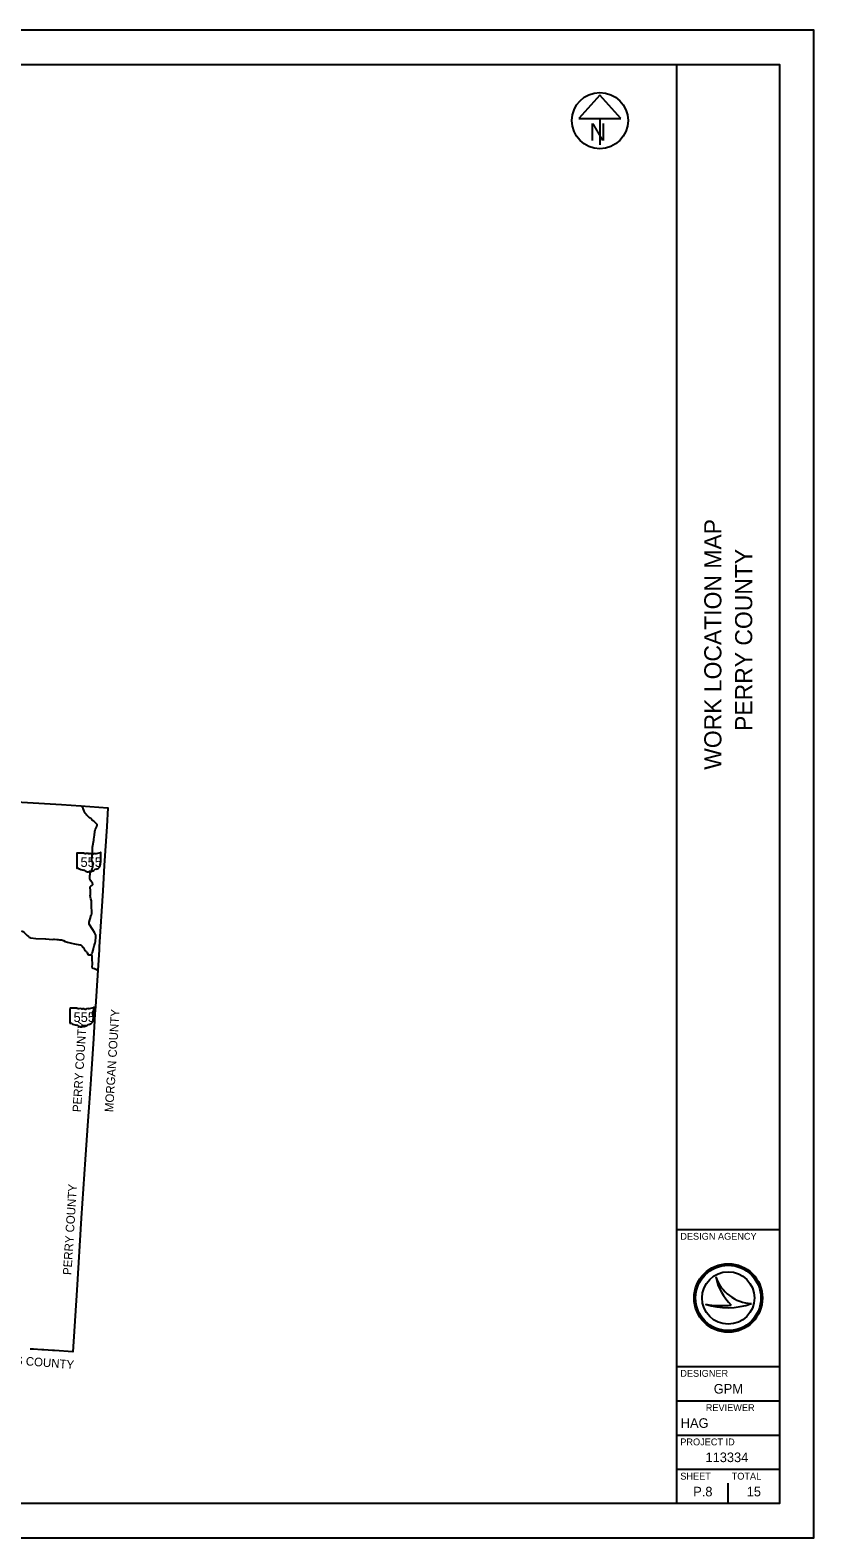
# Model space of a CAD drawing. Extents: x 1912787 to 2184787, y 78841 to 719251.
# Drawn here: x 2093246 to 2184787, y 543251 to 719251 of the extents above; entities that cross this region are included whole.
import ezdxf

# ---------------------------------------------------------------- set-up
doc = ezdxf.new("R2010")
doc.units = 0
for name, color, linetype in [('GM_X_County', 7, 'Continuous'), ('GM_X_County_Text', 7, 'Continuous'), ('GM_X_State_Location', 7, 'Continuous'), ('GM_X_State_Route', 7, 'Continuous'), ('GM_X_State_Shield', 7, 'Continuous'), ('SH_Border', 7, 'Continuous'), ('SH_Cut_Line', 7, 'Continuous'), ('SH_Data', 7, 'Continuous'), ('SH_Masking', 7, 'Continuous'), ('SH_Text', 7, 'Continuous')]:
    doc.layers.add(name, color=color, linetype=linetype)

msp = doc.modelspace()

# ---------------------------------------------------------------- linework, layer by layer
at = {"layer": 'GM_X_County'}
msp.add_lwpolyline([(2090938, 629224), (2096895, 628847), (2099187, 628710), (2102312, 628487), (2102193, 626283), (2101908, 621725), (2101721, 618763), (2101311, 612237), (2101290, 611908), (2101137, 609504), (2100881, 605294), (2100816, 604427), (2100776, 603648), (2100631, 601508), (2100343, 596816), (2100327, 596770), (2100147, 594037), (2099987, 591925), (2099681, 587430), (2099218, 580571), (2098707, 572170), (2098250, 564948), (2096075, 565106), (2095873, 565126), (2094827, 565192), (2094797, 565200), (2094779, 565204), (2094764, 565207), (2094750, 565209), (2094740, 565211), (2094727, 565212), (2094716, 565212), (2094701, 565213), (2094683, 565212), (2094668, 565211), (2094648, 565210), (2094631, 565207), (2094613, 565204), (2093651, 565260), (2093610, 565267), (2093571, 565272), (2093538, 565275), (2093505, 565278), (2093473, 565281), (2093444, 565283), (2093421, 565284), (2093383, 565286), (2093357, 565287), (2093335, 565287), (2093279, 565284), (2093242, 565282)], dxfattribs=at)
at = {"layer": 'GM_X_State_Route'}
for points in [[(2099600, 627994), (2099570, 628077), (2099522, 628214), (2099451, 628392), (2099374, 628518), (2099298, 628605), (2099188, 628707)], [(2101076, 626465), (2101081, 626479), (2101088, 626513), (2100994, 626609), (2100806, 626799), (2100700, 626898), (2100545, 626998), (2100502, 627052), (2100472, 627100), (2100453, 627131), (2100427, 627169), (2100408, 627187), (2100370, 627213), (2100312, 627242), (2100254, 627266), (2100196, 627297), (2100151, 627330), (2100111, 627364), (2099976, 627498), (2099922, 627559), (2099883, 627610), (2099831, 627677), (2099793, 627720), (2099748, 627765), (2099661, 627851), (2099626, 627921), (2099600, 627994)], [(2100572, 621814), (2100571, 621851), (2100568, 621979), (2100564, 622050), (2100492, 622189), (2100433, 622306), (2100418, 622362), (2100421, 622417), (2100438, 622470), (2100450, 622524), (2100481, 622839), (2100512, 623284), (2100512, 623462), (2100543, 623875), (2100669, 624702), (2100686, 624812), (2100760, 625292), (2100818, 625708), (2100851, 625884), (2100904, 626052), (2101021, 626309), (2101076, 626465)], [(2100227, 620259), (2100227, 620264), (2100229, 620349), (2100237, 620530), (2100238, 620563), (2100243, 620639), (2100243, 620701), (2100248, 620763), (2100256, 620821), (2100264, 620861), (2100289, 620950), (2100298, 620979), (2100310, 621008), (2100324, 621040), (2100336, 621063), (2100346, 621082), (2100374, 621129), (2100438, 621236), (2100484, 621313), (2100499, 621347), (2100508, 621372), (2100524, 621411), (2100538, 621450), (2100548, 621475), (2100552, 621492), (2100557, 621524), (2100560, 621544), (2100562, 621562), (2100566, 621601), (2100569, 621651), (2100569, 621699), (2100573, 621771), (2100572, 621814)], [(2100408, 611276), (2100464, 611414), (2100522, 611579), (2100591, 611844), (2100652, 612054), (2100742, 612343), (2100851, 612691), (2100894, 612858), (2100934, 613401), (2100932, 613525), (2100914, 613602), (2100870, 613699), (2100765, 613917), (2100585, 614226), (2100150, 614888), (2100131, 614961), (2100158, 615103), (2100330, 615799), (2100339, 615853), (2100350, 615895), (2100407, 616002), (2100438, 616062), (2100460, 616142), (2100427, 617136), (2100421, 617330), (2100428, 617496), (2100415, 617625), (2100354, 617832), (2100302, 618054), (2100274, 618180), (2100298, 618326), (2100309, 618521), (2100282, 618858), (2100241, 619116), (2100244, 619190), (2100271, 619254), (2100323, 619321), (2100558, 619494), (2100573, 619505), (2100586, 619514), (2100524, 619673), (2100407, 619847), (2100336, 619933), (2100281, 620014), (2100242, 620104), (2100237, 620123), (2100232, 620154), (2100228, 620186), (2100227, 620219), (2100227, 620259)], [(2092257, 614093), (2092407, 614019), (2092552, 613916), (2092757, 613724), (2092892, 613584), (2093069, 613433), (2093147, 613380), (2093234, 613338), (2093291, 613301), (2093344, 613282)], [(2093344, 613282), (2093921, 613233), (2095034, 613160)], [(2095034, 613160), (2095087, 613157), (2095851, 613117), (2096017, 613132), (2096109, 613128), (2096378, 613103), (2096525, 613096), (2096675, 613073), (2096929, 613058), (2097023, 613035), (2097154, 612983), (2097348, 612871), (2097595, 612783), (2098082, 612674), (2098421, 612602), (2098618, 612563), (2098871, 612516), (2099060, 612491), (2099171, 612457), (2099254, 612416), (2099326, 612338), (2099417, 612202), (2099470, 612148), (2099507, 612108), (2099565, 611968), (2099638, 611820), (2099691, 611762), (2099778, 611682), (2099849, 611607), (2099902, 611527), (2100011, 611349), (2100089, 611326), (2100275, 611300), (2100361, 611290), (2100408, 611276)], [(2100408, 611276), (2100432, 611248), (2100439, 611215), (2100444, 611101), (2100460, 610757), (2100484, 610316), (2100478, 610176), (2100465, 609961), (2100458, 609858), (2100465, 609825)], [(2100465, 609825), (2100485, 609797), (2100525, 609772), (2100578, 609761), (2100755, 609696), (2101138, 609501)], [(2100777, 603645), (2100702, 603918), (2100646, 604087), (2100602, 604252), (2100580, 604393), (2100579, 604512), (2100581, 604585), (2100597, 604681), (2100628, 604766), (2100667, 604862), (2100719, 604962), (2100882, 605291)]]:
    msp.add_lwpolyline(points, dxfattribs=at)
at = {"layer": 'GM_X_State_Shield'}
for p, q in [((2098713, 623153), (2098713, 621452)), ((2099561, 623182), (2098741, 623182)), ((2101515, 622334), (2101515, 623224)), ((2101515, 622334), (2101515, 622334)), ((2097900, 605048), (2097900, 603347)), ((2098748, 605077), (2097927, 605077)), ((2100701, 604230), (2100701, 605119)), ((2100701, 604230), (2100701, 604230))]:
    msp.add_line(p, q, dxfattribs=at)
for centre, major_axis, start_param, end_param in [((2098745, 623156), (32.5, 0), 1.7126934, 3.2834897), ((2099757, 623380), (315, 0), 4.042523, 4.731795), ((2099861, 622227), (1130, 0), 1.4047578, 1.6578581), ((2100118, 623165), (90.8, 0), 3.8360951, 5.1854146), ((2100251, 622969), (189, 0), 0.950623, 2.079405), ((2100495, 623238), (227, 0), 4.0815608, 5.1457227), ((2100896, 622662), (598, 0), 1.6990114, 2.1078141), ((2100517, 625501), (2971, 0), 4.8143942, 5.0423688), ((2101484, 623228), (31.2, 0), 6.1411519, 7.9890352), ((2098746, 621448), (32.7, 0), 3.00124, 4.5083009), ((2098751, 621622), (250, 0), 4.6659457, 4.8974612), ((2098802, 621353), (90.1, 0), 0.5192072, 1.6278991), ((2099939, 622882), (2146, 0), 4.1959971, 4.4889607), ((2100997, 620974), (407, 0), 1.6476453, 2.4884337), ((2100684, 621849), (743, 0), 5.1017525, 6.4400178), ((2101627, 621962), (211, 0), 2.3877238, 3.2625369), ((2101508, 622269), (48.3, 0), 1.8839779, 3.6710726), ((2101201, 622156), (290, 0), 5.9346948, 6.6959481), ((2101482, 622331), (33.4, 0), 5.05454, 6.4181714), ((2099300, 620687), (671, 0), 0.8235189, 1.3235874), ((2100026, 621345), (426, 0), 4.0264811, 4.9967352), ((2100272, 620757), (350, 0), 1.495662, 1.9409797), ((2100303, 621218), (227, 0), 4.6910439, 5.5073738), ((2100508, 621053), (63.9, 0), 1.1475842, 2.3151517), ((2100481, 621287), (240, 0), 4.9370686, 5.64225), ((2097932, 605052), (32.5, 0), 1.7126934, 3.2834897), ((2098943, 605275), (315, 0), 4.042523, 4.731795), ((2099047, 604122), (1130, 0), 1.4047578, 1.6578581), ((2099304, 605060), (90.8, 0), 3.8360951, 5.1854146), ((2099437, 604864), (189, 0), 0.950623, 2.079405), ((2099681, 605134), (227, 0), 4.0815608, 5.1457227), ((2100082, 604558), (598, 0), 1.6990114, 2.1078141), ((2099703, 607397), (2971, 0), 4.8143942, 5.0423688), ((2099870, 603744), (743, 0), 5.1017525, 6.4400178), ((2100813, 603857), (211, 0), 2.3877238, 3.2625369), ((2100694, 604164), (48.3, 0), 1.8839779, 3.6710726), ((2100387, 604052), (290, 0), 5.9346948, 6.6959481), ((2100670, 605123), (31.2, 0), 6.1411519, 7.9890352), ((2100668, 604226), (33.4, 0), 5.05454, 6.4181714), ((2097932, 603343), (32.7, 0), 3.00124, 4.5083009), ((2097937, 603517), (250, 0), 4.6659457, 4.8974612), ((2097988, 603249), (90.1, 0), 0.5192072, 1.6278991), ((2099126, 604777), (2146, 0), 4.1959971, 4.4889607), ((2098486, 602583), (671, 0), 0.8235189, 1.3235874), ((2099212, 603240), (426, 0), 4.0264811, 4.9967352), ((2099458, 602652), (350, 0), 1.495662, 1.9409797), ((2099489, 603113), (227, 0), 4.6910439, 5.5073738), ((2099695, 602948), (63.9, 0), 1.1475842, 2.3151517), ((2099667, 603182), (240, 0), 4.9370686, 5.64225), ((2100183, 602869), (407, 0), 1.6476453, 2.4884337)]:
    msp.add_ellipse(centre, major_axis=major_axis, ratio=0.8, start_param=start_param, end_param=end_param, dxfattribs=at)
at = {"layer": 'SH_Border'}
for p, q in [((2168787, 547251), (2168787, 715251)), ((2168787, 579251), (2180787, 579251)), ((2168787, 563251), (2180787, 563251)), ((2168787, 559251), (2180787, 559251)), ((2168787, 555251), (2180787, 555251)), ((2168787, 551251), (2180787, 551251))]:
    msp.add_line(p, q, dxfattribs=at)
msp.add_lwpolyline([(1924787, 715251), (2180787, 715251), (2180787, 547251), (1924787, 547251)], close=True, dxfattribs=at)
at = {"layer": 'SH_Cut_Line'}
msp.add_lwpolyline([(1912787, 543251), (2184787, 543251), (2184787, 719251), (1912787, 719251)], close=True, dxfattribs=at)
at = {"layer": 'SH_Data'}
for p, q in [((2173326, 573727), (2173326, 573727)), ((2172124, 570527), (2172124, 570527)), ((2174787, 571251), (2174787, 571251)), ((2177485, 570599), (2177485, 570599)), ((2174787, 547251), (2174787, 549651)), ((2171787, 548651), (2171787, 548651))]:
    msp.add_line(p, q, dxfattribs=at)
for radius in [4000, 3814, 3814, 3058]:
    msp.add_circle((2174787, 571251), radius, dxfattribs=at)
for centre, radius, start, end in [((2177714, 575232), 4639, 198.92567, 198.93195), ((2179560, 575011), 6365, 191.63793, 191.64215), ((2177714, 575232), 4639, 198.93195, 267.16574), ((2179560, 575011), 6365, 191.64215, 226.09467), ((2173971, 580486), 10128, 259.49639, 259.49952), ((2174702, 578211), 8105, 251.45274, 251.45764), ((2174702, 578211), 8105, 251.45764, 290.08324), ((2173971, 580486), 10128, 259.49952, 276.66723)]:
    msp.add_arc(centre, radius, start, end, dxfattribs=at)
at = {"layer": 'SH_Masking'}
msp.add_circle((2159798, 708690), 3280, dxfattribs=at)
at = {"layer": 'SH_Text'}
for p, q in [((2159798, 711680), (2157337, 708950)), ((2162259, 708950), (2159798, 711680)), ((2157337, 708950), (2162259, 708950)), ((2159798, 708950), (2159798, 705856))]:
    msp.add_line(p, q, dxfattribs=at)
msp.add_circle((2159798, 708690), 3280, dxfattribs=at)

# ---------------------------------------------------------------- texts
at = {"layer": 'GM_X_County_Text'}
for s, rotation, p in [('MORGAN COUNTY', 86.46062, (2102945, 592922)), ('PERRY COUNTY', 86.46062, (2099187, 592922)), ('PERRY COUNTY', 86.41019, (2098062, 573907)), ('ATHENS COUNTY', 355.51231, (2086932, 563846))]:
    msp.add_text(s, height=1000, rotation=rotation, dxfattribs=at).set_placement(p)
at = {"layer": 'GM_X_State_Location'}
for p in [(2100056, 622307), (2100777, 607246), (2100228, 604293)]:
    msp.add_text('555', height=1, rotation=0.00001, dxfattribs=at).set_placement(p)
for s, p in [('s', (2100409, 622380)), ('r', (2100409, 622380)), ('s', (2101130, 607319)), ('r', (2101130, 607319)), ('s', (2100581, 604366)), ('r', (2100581, 604366))]:
    msp.add_text(s, height=1, dxfattribs=at).set_placement(p)
at = {"layer": 'GM_X_State_Shield'}
for p in [(2099131, 621572), (2098317, 603467)]:
    msp.add_text('555', height=1120.7, dxfattribs=at).set_placement(p)
at = {"layer": 'SH_Data'}
for s, p in [('WORK LOCATION MAP', (2173987, 632909)), ('PERRY COUNTY', (2177587, 637447))]:
    msp.add_text(s, height=2000, rotation=90, dxfattribs=at).set_placement(p)
for s, height, p in [('DESIGN AGENCY', 800, (2169187, 578051)), ('DESIGNER', 800, (2169187, 562051)), ('GPM', 1120, (2173094, 560091)), ('REVIEWER', 800, (2172161, 558051)), ('HAG', 1120, (2169240, 556091)), ('PROJECT ID', 800, (2169187, 554051)), ('113334', 1120, (2172130, 552091)), ('SHEET', 800, (2169187, 550051)), ('P.8', 1120, (2170697, 548091)), ('TOTAL', 800, (2175187, 550051)), ('15', 1120, (2176944, 548091))]:
    msp.add_text(s, height=height, dxfattribs=at).set_placement(p)
at = {"layer": 'SH_Text'}
msp.add_text('N', height=2000, dxfattribs=at).set_placement((2158588, 706359))

doc.saveas('drawing.dxf')
